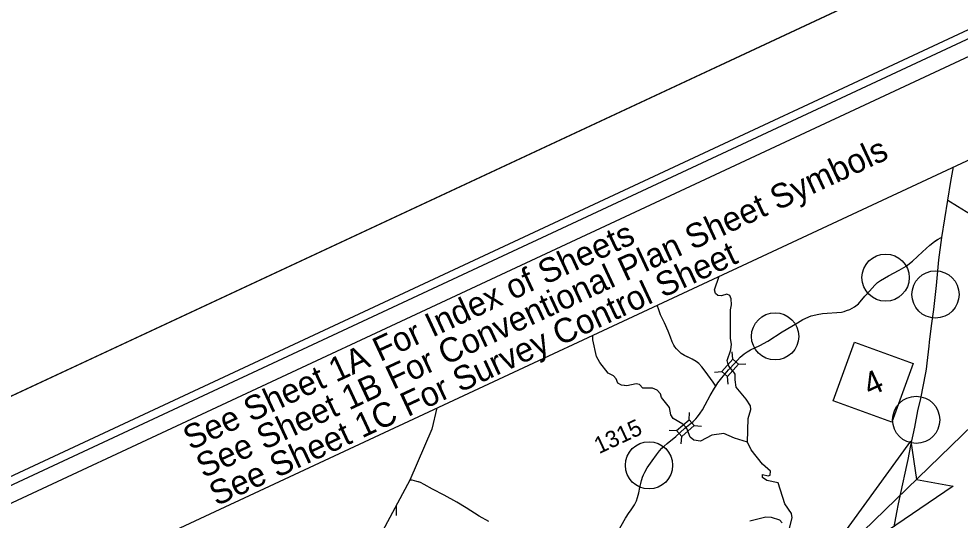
# Model space of a CAD drawing. Extents: x 2318983 to 2324558, y 920396 to 924651.
# Drawn here: x 2320105 to 2320803, y 923112 to 923483 of the extents above; entities that cross this region are included whole.
import ezdxf

# ---------------------------------------------------------------- set-up
doc = ezdxf.new("R2010")
doc.units = 0
for name, color, linetype in [('Exist Boundary Political CountyLine', 7, 'Continuous'), ('Exist Hydrographic Creek Single Shore', 7, 'Continuous'), ('Exist Road Primary NC Attributed', 7, 'Continuous'), ('Exist Road Primary NC Shield CELL', 7, 'Continuous'), ('Exist Road Primary NC Shield Number Label', 7, 'Continuous'), ('Exist Road Secondary Structure Standard Bridge CELL', 7, 'Continuous'), ('Exist Road Secondary Type 51 Attributed', 7, 'Continuous'), ('Exist Road Secondary Type 51 Number Label', 7, 'Continuous'), ('Pattern 3', 7, 'Continuous'), ('Prop Terminator CELL', 7, 'Continuous'), ('Sheet Cutting Line CELL', 7, 'Continuous'), ('Sheet Plot Border Inside CELL', 7, 'Continuous'), ('Sheet Plot Border Outside CELL', 7, 'Continuous'), ('Sheet Title CELL', 7, 'Continuous')]:
    doc.layers.add(name, color=color, linetype=linetype)

msp = doc.modelspace()

# ---------------------------------------------------------------- linework, layer by layer
at = {"layer": 'Exist Boundary Political CountyLine'}
msp.add_lwpolyline([(2320414.68, 923194.83), (2320410.98, 923178.95), (2320394.65, 923141.22), (2320377.91, 923110.4), (2320358.36, 923073.81), (2320329.75, 923021.28), (2320285.07, 922937.61), (2320259.09, 922888.55), (2320253.04, 922876.5), (2320238.46, 922848.27), (2320218.02, 922812.6)], dxfattribs=at)
at = {"layer": 'Exist Hydrographic Creek Single Shore'}
for points in [[(2320633.2, 923271.3), (2320632.75, 923275.64), (2320631.89, 923278.11), (2320629.63, 923279.06), (2320625.75, 923278.02), (2320622.89, 923278.14), (2320621.21, 923279.77), (2320620.57, 923282.49), (2320623.99, 923292.51)], [(2320644.96, 923169.38), (2320645.38, 923187), (2320647.57, 923193.55), (2320647.13, 923196.28), (2320644, 923201.32), (2320636.52, 923210.3), (2320635.89, 923215.68), (2320635.89, 923219.91), (2320634.96, 923221.45), (2320632.2, 923224.47), (2320631.02, 923225.72), (2320630.57, 923226.94), (2320629.95, 923229.9), (2320632.54, 923237.92), (2320633.1, 923241.98), (2320632.43, 923246.31), (2320632.41, 923267.63), (2320633.2, 923271.3)], [(2320555.55, 923211.25), (2320551.66, 923211.66), (2320548.76, 923213.23), (2320547.5, 923216.5), (2320545.63, 923218.52), (2320541.72, 923220.54), (2320535.49, 923228.44), (2320532.99, 923232.94), (2320530.38, 923245.19), (2320530.34, 923248.81)], [(2320644.96, 923169.38), (2320645.38, 923187), (2320647.57, 923193.55), (2320647.13, 923196.28), (2320644, 923201.32), (2320636.52, 923210.3), (2320635.89, 923215.68), (2320635.89, 923219.91), (2320634.96, 923221.45), (2320632.2, 923224.47), (2320631.02, 923225.72), (2320630.57, 923226.94), (2320629.95, 923229.9), (2320632.54, 923237.92), (2320633.1, 923241.98), (2320632.43, 923246.31), (2320632.43, 923248.02)], [(2320555.55, 923211.25), (2320554, 923211.42)], [(2320644.96, 923169.38), (2320635.29, 923172.37), (2320627.47, 923175.77), (2320618.46, 923174.59), (2320610.1, 923170.05), (2320605.18, 923170.82), (2320602.49, 923173.05), (2320599.91, 923179.61), (2320599.43, 923180.41), (2320597.09, 923182.66), (2320589.82, 923187.06), (2320588.17, 923189.66), (2320587.09, 923195.02), (2320581.26, 923202.54), (2320580.43, 923205.33), (2320577.94, 923207.97), (2320574.42, 923209.45), (2320567.26, 923209.55), (2320564.78, 923212.2), (2320562.51, 923212.75), (2320555.55, 923211.25)], [(2320675.2, 923101.66), (2320678.15, 923113.32), (2320677.71, 923116.46), (2320672.71, 923123.76), (2320667.62, 923139.3), (2320659.41, 923141.06), (2320656.11, 923143.27), (2320656.08, 923145.53), (2320660.39, 923144.5), (2320661.82, 923144.96), (2320661.99, 923147.79), (2320655.99, 923153.12), (2320647.69, 923163.84), (2320644.96, 923169.38)], [(2320646.61, 923110.98), (2320658.66, 923113.98), (2320662.55, 923113.82), (2320668.73, 923111.81), (2320670.6, 923109.62)]]:
    msp.add_lwpolyline(points, dxfattribs=at)
at = {"layer": 'Exist Road Primary NC Attributed'}
msp.add_line((2320789.17, 923321.31), (2320793.54, 923348.78), dxfattribs=at)
for points in [[(2320793.54, 923348.78), (2320795.74, 923362.71), (2320797.84, 923373.65)], [(2320753.71, 923106.59), (2320755.77, 923117.28), (2320756.99, 923123.58), (2320758.93, 923132.81), (2320763.11, 923152.09), (2320764.05, 923156.62), (2320766.17, 923166.83), (2320769, 923180.45), (2320771.38, 923192.6), (2320773.41, 923201.91), (2320777.26, 923220.74), (2320777.71, 923223.51), (2320778.29, 923228.06), (2320779.78, 923240.59), (2320780.08, 923243.52), (2320781.35, 923255.76), (2320783.09, 923267.82), (2320785.17, 923285.66), (2320786.93, 923304.6), (2320789.17, 923321.31)]]:
    msp.add_lwpolyline(points, dxfattribs=at)
at = {"layer": 'Exist Road Primary NC Shield CELL'}
for p, q in [((2320708.46, 923199.96), (2320724.29, 923243.52)), ((2320724.29, 923243.52), (2320767.85, 923227.68)), ((2320767.85, 923227.68), (2320752.01, 923184.13)), ((2320752.01, 923184.13), (2320708.46, 923199.96))]:
    msp.add_line(p, q, dxfattribs=at)
at = {"layer": 'Exist Road Secondary Structure Standard Bridge CELL'}
for p, q in [((2320634.01, 923230.91), (2320633.64, 923236.46)), ((2320620.39, 923221.39), (2320625.95, 923221.75)), ((2320638.2, 923227.24), (2320643.75, 923227.6)), ((2320630.6, 923212.44), (2320630.23, 923218)), ((2320601.65, 923185.97), (2320602.03, 923191.53)), ((2320605.31, 923181.77), (2320610.87, 923181.39)), ((2320586.89, 923178.35), (2320592.44, 923177.97)), ((2320595.81, 923168.12), (2320596.19, 923173.68))]:
    msp.add_line(p, q, dxfattribs=at)
for points in [[(2320625.95, 923221.75), (2320633.99, 923230.92), (2320638.27, 923227.17), (2320630.23, 923218)], [(2320592.44, 923177.97), (2320601.64, 923185.99), (2320605.38, 923181.69), (2320596.19, 923173.68)]]:
    msp.add_lwpolyline(points, close=True, dxfattribs=at)
at = {"layer": 'Exist Road Secondary Type 51 Attributed'}
msp.add_line((2320384.44, 923122.43), (2320384.53, 923115.07), dxfattribs=at)
for points in [[(2320793.54, 923348.78), (2320800.65, 923344.5), (2320810.3, 923338.55), (2320820.15, 923332.15), (2320823.7, 923329.91), (2320826.63, 923327.79), (2320828.46, 923326.12), (2320830.86, 923323.06), (2320837.01, 923314.83), (2320842.14, 923308.51), (2320842.92, 923307.62), (2320843.98, 923306.8), (2320844.75, 923306.31), (2320846.05, 923305.87), (2320846.79, 923305.74), (2320848.21, 923305.7), (2320851.1, 923305.7), (2320855.87, 923305.87)], [(2320630.83, 923222.98), (2320635.8, 923228.34), (2320639.58, 923232.53), (2320642.55, 923234.96), (2320644.71, 923236.44), (2320647.2, 923237.79), (2320654.23, 923241.23), (2320660.09, 923244.44), (2320670.61, 923251.16), (2320682, 923257.82), (2320686.1, 923260.33), (2320692.2, 923263.01), (2320693.55, 923263.45), (2320696.59, 923264.19), (2320700.57, 923264.83), (2320714.79, 923265.91), (2320716.71, 923266.36), (2320718.31, 923266.99), (2320720.8, 923267.93), (2320724.24, 923269.69), (2320727.21, 923272.12), (2320731.93, 923277.59), (2320735.37, 923281.47), (2320739.35, 923285.86), (2320741.51, 923287.95), (2320743.54, 923289.23), (2320749.54, 923292.68), (2320757.43, 923297.1), (2320762.71, 923299.87), (2320767.42, 923303.65), (2320774.87, 923310.63), (2320780.21, 923315.4), (2320783.67, 923318.17), (2320786.31, 923320.05), (2320788.11, 923320.9), (2320789.17, 923321.31)], [(2320630.83, 923222.98), (2320635.8, 923228.34), (2320639.58, 923232.53), (2320642.55, 923234.96), (2320644.71, 923236.44), (2320647.2, 923237.79), (2320654.23, 923241.23), (2320660.09, 923244.44), (2320670.61, 923251.16), (2320682, 923257.82), (2320686.1, 923260.33), (2320692.2, 923263.01), (2320693.55, 923263.45), (2320696.59, 923264.19), (2320700.57, 923264.83), (2320714.79, 923265.91), (2320716.71, 923266.36), (2320718.31, 923266.99), (2320720.8, 923267.93), (2320724.24, 923269.69), (2320727.21, 923272.12), (2320731.93, 923277.59), (2320735.37, 923281.47), (2320739.35, 923285.86), (2320741.51, 923287.95), (2320743.54, 923289.23), (2320749.54, 923292.68), (2320757.43, 923297.1), (2320762.71, 923299.87), (2320767.42, 923303.65), (2320774.87, 923310.63), (2320780.21, 923315.4), (2320783.67, 923318.17), (2320785.44, 923319.43)], [(2320621.38, 923211.07), (2320619.51, 923213.82), (2320613.62, 923222.11), (2320611.19, 923225.29), (2320608.82, 923227.75), (2320606.87, 923229.31), (2320603.9, 923230.9), (2320598.24, 923233.61), (2320595.82, 923235.11), (2320594.48, 923236.32), (2320593.23, 923237.54), (2320592.28, 923238.66), (2320591.1, 923240.22), (2320590.43, 923241.44), (2320589.08, 923243.91), (2320587.82, 923247.2), (2320586.05, 923251.77), (2320583.32, 923257.94), (2320580.58, 923263.96), (2320579.23, 923267.47), (2320577.93, 923271.02)], [(2320621.38, 923211.07), (2320619.51, 923213.82), (2320613.62, 923222.11), (2320611.19, 923225.29), (2320608.82, 923227.75), (2320606.87, 923229.31), (2320603.9, 923230.9), (2320599.88, 923232.83)], [(2320621.38, 923211.07), (2320623, 923213.41), (2320625.85, 923217.07), (2320630.83, 923222.98)], [(2320598.6, 923179.69), (2320604.62, 923184.74), (2320606.72, 923186.81), (2320607.83, 923188.13), (2320609.9, 923190.86), (2320611.64, 923193.44), (2320613.65, 923197.07), (2320617.37, 923203.96), (2320620.42, 923209.48), (2320621.38, 923211.07)], [(2320547.12, 923100.03), (2320554.4, 923112.93), (2320557.22, 923117.16), (2320558.15, 923118.45), (2320558.78, 923119.35), (2320561.12, 923122.96), (2320562.59, 923125.78), (2320563.52, 923128.42), (2320564.51, 923131.75), (2320565.26, 923135.69), (2320565.92, 923138.78), (2320566.43, 923141.03), (2320566.71, 923141.62), (2320567.15, 923143.38), (2320567.75, 923145.24), (2320568.85, 923147.25), (2320570.62, 923150.34), (2320574.28, 923155.62), (2320577.46, 923160), (2320579.83, 923162.91), (2320581.54, 923164.92), (2320583.28, 923166.48), (2320585.37, 923168.31), (2320591.88, 923173.69), (2320598.6, 923179.69)], [(2320453.18, 923110.6), (2320446.05, 923114.6), (2320436.37, 923120.6), (2320429.33, 923124.84), (2320419.92, 923130.07), (2320411.48, 923134.64), (2320405.2, 923138.04), (2320402.38, 923139.54), (2320399.86, 923140.36), (2320397.91, 923140.84), (2320396.24, 923141.18), (2320394.66, 923141.23)], [(2320453.18, 923110.6), (2320446.05, 923114.6), (2320436.37, 923120.6), (2320429.33, 923124.84), (2320419.92, 923130.07), (2320411.48, 923134.64), (2320405.2, 923138.04), (2320402.38, 923139.54), (2320400.97, 923140)]]:
    msp.add_lwpolyline(points, dxfattribs=at)
at = {"layer": 'Pattern 3'}
for p, q in [((2320106.71, 923051.1), (2320981.79, 923459.5)), ((2320812.16, 923182.33), (2320687.87, 923062.03))]:
    msp.add_line(p, q, dxfattribs=at)
for centre in [(2320747.4, 923291.45), (2320784.39, 923278.97), (2320665.45, 923247.87), (2320770.08, 923185.96), (2320571.95, 923152.25)]:
    msp.add_circle(centre, 17.51, dxfattribs=at)
at = {"layer": 'Prop Terminator CELL'}
msp.add_lwpolyline([(2320797.42, 923136.74), (2320687.87, 923062.03), (2320766.13, 923170.11), (2320770.29, 923141.81)], close=True, dxfattribs=at)
at = {"layer": 'Sheet Cutting Line CELL'}
msp.add_line((2319538.32, 922941.96), (2323200.7, 924651.2), dxfattribs=at)
at = {"layer": 'Sheet Plot Border Inside CELL'}
msp.add_lwpolyline([(2320660.3, 920611.69), (2324284.61, 922303.17), (2323213.7, 924597.81), (2319589.38, 922906.33)], close=True, dxfattribs=at)
at = {"layer": 'Sheet Plot Border Outside CELL'}
msp.add_lwpolyline([(2323200.7, 924651.2), (2319538.32, 922941.96), (2320654.8, 920549.69), (2324317.18, 922258.94)], close=True, dxfattribs=at)
at = {"layer": 'Sheet Title CELL'}
for points in [[(2323167.38, 924569.44), (2319948.6, 923067.25)], [(2323161.55, 924553.48), (2320073.35, 923112.2)]]:
    msp.add_lwpolyline(points, dxfattribs=at)

# ---------------------------------------------------------------- texts
at = {"layer": 'Exist Road Primary NC Shield Number Label'}
msp.add_text('4', height=17.22, rotation=25.01869, dxfattribs=at).set_placement((2320735.84, 923203))
at = {"layer": 'Exist Road Secondary Type 51 Number Label'}
msp.add_text('1315', height=12.302, rotation=25.01869, dxfattribs=at).set_placement((2320534.83, 923160.46))
at = {"layer": 'Sheet Title CELL'}
for s, p in [('See Sheet 1B For Conventional Plan Sheet Symbols', (2320241.49, 923142.43)), ('See Sheet 1A For Index of Sheets', (2320231.84, 923163.11)), ('See Sheet 1C For Survey Control Sheet', (2320251.15, 923121.75))]:
    msp.add_text(s, height=18, rotation=25.01869, dxfattribs=at).set_placement(p)

doc.saveas('drawing.dxf')
